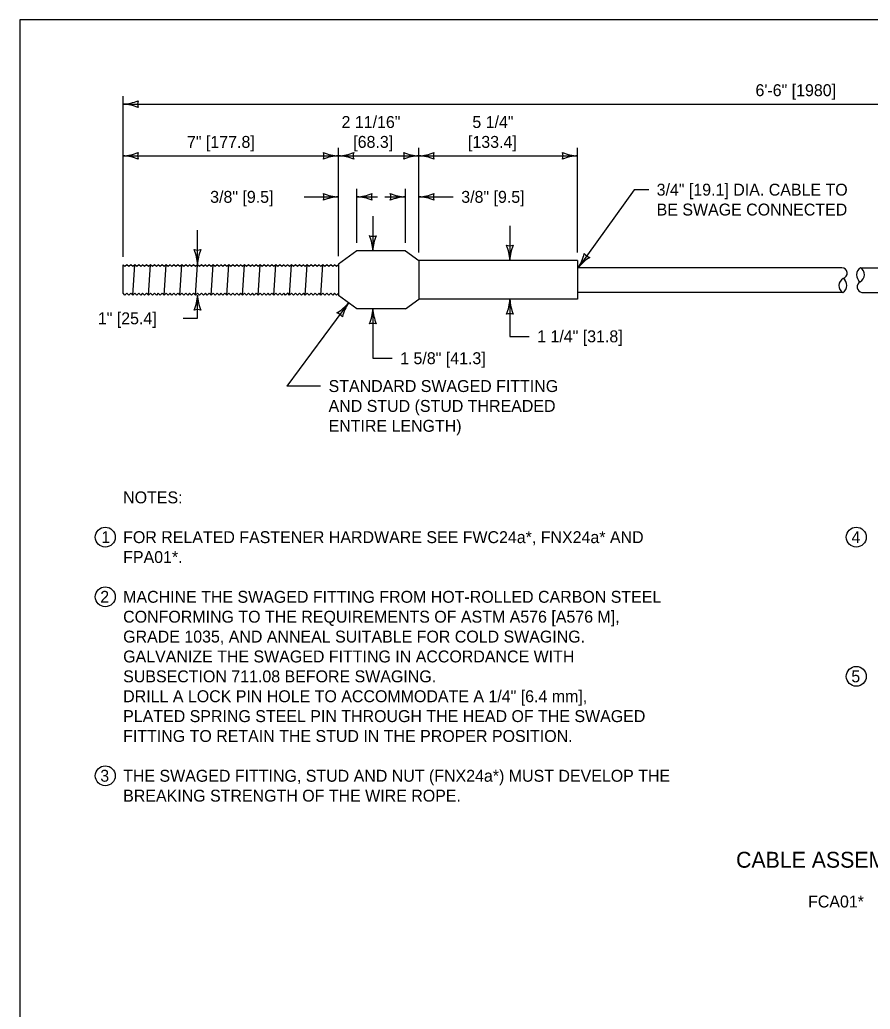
# Model space of a CAD drawing. Extents: x 49991.4 to 50021, y 49987.6 to 50011.4.
# Drawn here: x 50000.336 to 50004.612, y 50006.287 to 50011.263 of the extents above; entities that cross this region are included whole.
import ezdxf

# ---------------------------------------------------------------- set-up
doc = ezdxf.new("R2010")
doc.units = 0
for name, color, linetype in [('Level 1', 7, 'Continuous'), ('Level 2', 7, 'Continuous'), ('Level 3', 7, 'Continuous')]:
    doc.layers.add(name, color=color, linetype=linetype)

msp = doc.modelspace()

# ---------------------------------------------------------------- linework, layer by layer
at = {"layer": 'Level 1'}
for p, q in [((50002.0304, 50010.1011), (50001.9386, 50010.0335)), ((50002.2748, 50010.1011), (50002.0304, 50010.1011)), ((50002.2748, 50010.1011), (50002.3422, 50010.0531)), ((50002.3422, 50010.0531), (50002.3422, 50009.8577)), ((50003.1408, 50010.0531), (50002.3422, 50010.0531)), ((50003.1408, 50010.0531), (50003.1408, 50009.8577)), ((50000.8542, 50010.0181), (50000.8542, 50009.8915)), ((50000.8542, 50010.0181), (50000.8546, 50010.0181)), ((50000.8642, 50010.0213), (50000.8546, 50010.0311)), ((50000.8546, 50009.8883), (50000.8546, 50010.0311)), ((50000.8742, 50010.0311), (50000.8642, 50010.0213)), ((50000.8842, 50010.0213), (50000.8742, 50010.0311)), ((50000.8938, 50010.0311), (50000.8842, 50010.0213)), ((50000.9036, 50010.0213), (50000.8938, 50010.0311)), ((50000.9138, 50010.0311), (50000.9036, 50010.0213)), ((50000.9036, 50009.8785), (50000.9138, 50010.0311)), ((50000.9238, 50010.0213), (50000.9138, 50010.0311)), ((50000.9336, 50010.0311), (50000.9238, 50010.0213)), ((50000.9436, 50010.0213), (50000.9336, 50010.0311)), ((50000.9532, 50010.0311), (50000.9436, 50010.0213)), ((50000.963, 50010.0213), (50000.9532, 50010.0311)), ((50000.973, 50010.0311), (50000.963, 50010.0213)), ((50000.9828, 50010.0213), (50000.973, 50010.0311)), ((50000.9926, 50010.0311), (50000.9828, 50010.0213)), ((50000.9828, 50009.8785), (50000.9926, 50010.0311)), ((50001.0024, 50010.0213), (50000.9926, 50010.0311)), ((50001.0122, 50010.0311), (50001.0024, 50010.0213)), ((50001.0222, 50010.0213), (50001.0122, 50010.0311)), ((50001.032, 50010.0311), (50001.0222, 50010.0213)), ((50001.0418, 50010.0213), (50001.032, 50010.0311)), ((50001.0516, 50010.0311), (50001.0418, 50010.0213)), ((50001.0616, 50010.0213), (50001.0516, 50010.0311)), ((50001.0714, 50010.0311), (50001.0616, 50010.0213)), ((50001.0616, 50009.8785), (50001.0714, 50010.0311)), ((50001.0812, 50010.0213), (50001.0714, 50010.0311)), ((50001.091, 50010.0311), (50001.0812, 50010.0213)), ((50001.1008, 50010.0213), (50001.091, 50010.0311)), ((50001.1108, 50010.0311), (50001.1008, 50010.0213)), ((50001.1206, 50010.0213), (50001.1108, 50010.0311)), ((50001.1304, 50010.0311), (50001.1206, 50010.0213)), ((50001.1404, 50010.0213), (50001.1304, 50010.0311)), ((50001.1502, 50010.0311), (50001.1404, 50010.0213)), ((50001.1404, 50009.8785), (50001.1502, 50010.0311)), ((50001.1598, 50010.0213), (50001.1502, 50010.0311)), ((50001.1702, 50010.0311), (50001.1598, 50010.0213)), ((50001.1802, 50010.0213), (50001.1702, 50010.0311)), ((50001.1898, 50010.0311), (50001.1802, 50010.0213)), ((50001.1998, 50010.0213), (50001.1898, 50010.0311)), ((50001.2096, 50010.0311), (50001.1998, 50010.0213)), ((50001.2192, 50010.0213), (50001.2096, 50010.0311)), ((50001.2292, 50010.0311), (50001.2192, 50010.0213)), ((50001.2192, 50009.8785), (50001.2292, 50010.0311)), ((50001.239, 50010.0213), (50001.2292, 50010.0311)), ((50001.2488, 50010.0311), (50001.239, 50010.0213)), ((50001.2586, 50010.0213), (50001.2488, 50010.0311)), ((50001.2686, 50010.0311), (50001.2586, 50010.0213)), ((50001.2786, 50010.0213), (50001.2686, 50010.0311)), ((50001.2882, 50010.0311), (50001.2786, 50010.0213)), ((50001.298, 50010.0213), (50001.2882, 50010.0311)), ((50001.3078, 50010.0311), (50001.298, 50010.0213)), ((50001.298, 50009.8785), (50001.3078, 50010.0311)), ((50001.3178, 50010.0213), (50001.3078, 50010.0311)), ((50001.3276, 50010.0311), (50001.3178, 50010.0213)), ((50001.3374, 50010.0213), (50001.3276, 50010.0311)), ((50001.3472, 50010.0311), (50001.3374, 50010.0213)), ((50001.3572, 50010.0213), (50001.3472, 50010.0311)), ((50001.367, 50010.0311), (50001.3572, 50010.0213)), ((50001.3768, 50010.0213), (50001.367, 50010.0311)), ((50001.3866, 50010.0311), (50001.3768, 50010.0213)), ((50001.3768, 50009.8785), (50001.3866, 50010.0311)), ((50001.3966, 50010.0213), (50001.3866, 50010.0311)), ((50001.4064, 50010.0311), (50001.3966, 50010.0213)), ((50001.4162, 50010.0213), (50001.4064, 50010.0311)), ((50001.4264, 50010.0311), (50001.4162, 50010.0213)), ((50001.4364, 50010.0213), (50001.4264, 50010.0311)), ((50001.446, 50010.0311), (50001.4364, 50010.0213)), ((50001.456, 50010.0213), (50001.446, 50010.0311)), ((50001.4658, 50010.0311), (50001.456, 50010.0213)), ((50001.456, 50009.8785), (50001.4658, 50010.0311)), ((50001.4756, 50010.0213), (50001.4658, 50010.0311)), ((50001.4856, 50010.0311), (50001.4756, 50010.0213)), ((50001.4952, 50010.0213), (50001.4856, 50010.0311)), ((50001.5052, 50010.0311), (50001.4952, 50010.0213)), ((50001.5148, 50010.0213), (50001.5052, 50010.0311)), ((50001.5248, 50010.0311), (50001.5148, 50010.0213)), ((50001.5348, 50010.0213), (50001.5248, 50010.0311)), ((50001.5446, 50010.0311), (50001.5348, 50010.0213)), ((50001.5348, 50009.8785), (50001.5446, 50010.0311)), ((50001.5542, 50010.0213), (50001.5446, 50010.0311)), ((50001.5642, 50010.0311), (50001.5542, 50010.0213)), ((50001.574, 50010.0213), (50001.5642, 50010.0311)), ((50001.5838, 50010.0311), (50001.574, 50010.0213)), ((50001.5936, 50010.0213), (50001.5838, 50010.0311)), ((50001.6036, 50010.0311), (50001.5936, 50010.0213)), ((50001.6134, 50010.0213), (50001.6036, 50010.0311)), ((50001.6232, 50010.0311), (50001.6134, 50010.0213)), ((50001.6134, 50009.8785), (50001.6232, 50010.0311)), ((50001.633, 50010.0213), (50001.6232, 50010.0311)), ((50001.6428, 50010.0311), (50001.633, 50010.0213)), ((50001.6528, 50010.0213), (50001.6428, 50010.0311)), ((50001.6626, 50010.0311), (50001.6528, 50010.0213)), ((50001.6724, 50010.0213), (50001.6626, 50010.0311)), ((50001.6826, 50010.0311), (50001.6724, 50010.0213)), ((50001.6926, 50010.0213), (50001.6826, 50010.0311)), ((50001.7022, 50010.0311), (50001.6926, 50010.0213)), ((50001.6926, 50009.8785), (50001.7022, 50010.0311)), ((50001.7122, 50010.0213), (50001.7022, 50010.0311)), ((50001.722, 50010.0311), (50001.7122, 50010.0213)), ((50001.7318, 50010.0213), (50001.722, 50010.0311)), ((50001.7418, 50010.0311), (50001.7318, 50010.0213)), ((50001.7516, 50010.0213), (50001.7418, 50010.0311)), ((50001.7614, 50010.0311), (50001.7516, 50010.0213)), ((50001.7712, 50010.0213), (50001.7614, 50010.0311)), ((50001.781, 50010.0311), (50001.7712, 50010.0213)), ((50001.7712, 50009.8785), (50001.781, 50010.0311)), ((50001.791, 50010.0213), (50001.781, 50010.0311)), ((50001.8008, 50010.0311), (50001.791, 50010.0213)), ((50001.8106, 50010.0213), (50001.8008, 50010.0311)), ((50001.8204, 50010.0311), (50001.8106, 50010.0213)), ((50001.8302, 50010.0213), (50001.8204, 50010.0311)), ((50001.8402, 50010.0311), (50001.8302, 50010.0213)), ((50001.8498, 50010.0213), (50001.8402, 50010.0311)), ((50001.8598, 50010.0311), (50001.8498, 50010.0213)), ((50001.8498, 50009.8785), (50001.8598, 50010.0311)), ((50001.8696, 50010.0213), (50001.8598, 50010.0311)), ((50001.8796, 50010.0311), (50001.8696, 50010.0213)), ((50001.8892, 50010.0213), (50001.8796, 50010.0311)), ((50001.8992, 50010.0311), (50001.8892, 50010.0213)), ((50001.909, 50010.0213), (50001.8992, 50010.0311)), ((50001.9188, 50010.0311), (50001.909, 50010.0213)), ((50001.9286, 50010.0213), (50001.9188, 50010.0311)), ((50001.9386, 50010.0311), (50001.9286, 50010.0213)), ((50001.9386, 50010.0335), (50001.9386, 50009.8771)), ((50004.4692, 50010.0157), (50003.1408, 50010.0157)), ((50004.5624, 50010.0157), (50005.8048, 50010.0157)), ((50000.8542, 50009.8915), (50000.8546, 50009.8915)), ((50000.8642, 50009.8785), (50000.8546, 50009.8883)), ((50000.8742, 50009.8883), (50000.8642, 50009.8785)), ((50000.8842, 50009.8785), (50000.8742, 50009.8883)), ((50000.8938, 50009.8883), (50000.8842, 50009.8785)), ((50000.9036, 50009.8785), (50000.8938, 50009.8883)), ((50000.9138, 50009.8883), (50000.9036, 50009.8785)), ((50000.9238, 50009.8785), (50000.9138, 50009.8883)), ((50000.9336, 50009.8883), (50000.9238, 50009.8785)), ((50000.9436, 50009.8785), (50000.9336, 50009.8883)), ((50000.9532, 50009.8883), (50000.9436, 50009.8785)), ((50000.963, 50009.8785), (50000.9532, 50009.8883)), ((50000.973, 50009.8883), (50000.963, 50009.8785)), ((50000.9828, 50009.8785), (50000.973, 50009.8883)), ((50000.9926, 50009.8883), (50000.9828, 50009.8785)), ((50001.0024, 50009.8785), (50000.9926, 50009.8883)), ((50001.0122, 50009.8883), (50001.0024, 50009.8785)), ((50001.0222, 50009.8785), (50001.0122, 50009.8883)), ((50001.032, 50009.8883), (50001.0222, 50009.8785)), ((50001.0418, 50009.8785), (50001.032, 50009.8883)), ((50001.0516, 50009.8883), (50001.0418, 50009.8785)), ((50001.0616, 50009.8785), (50001.0516, 50009.8883)), ((50001.0714, 50009.8883), (50001.0616, 50009.8785)), ((50001.0812, 50009.8785), (50001.0714, 50009.8883)), ((50001.091, 50009.8883), (50001.0812, 50009.8785)), ((50001.1008, 50009.8785), (50001.091, 50009.8883)), ((50001.1108, 50009.8883), (50001.1008, 50009.8785)), ((50001.1206, 50009.8785), (50001.1108, 50009.8883)), ((50001.1304, 50009.8883), (50001.1206, 50009.8785)), ((50001.1404, 50009.8785), (50001.1304, 50009.8883)), ((50001.1502, 50009.8883), (50001.1404, 50009.8785)), ((50001.1598, 50009.8785), (50001.1502, 50009.8883)), ((50001.1702, 50009.8883), (50001.1598, 50009.8785)), ((50001.1802, 50009.8785), (50001.1702, 50009.8883)), ((50001.1898, 50009.8883), (50001.1802, 50009.8785)), ((50001.1998, 50009.8785), (50001.1898, 50009.8883)), ((50001.2096, 50009.8883), (50001.1998, 50009.8785)), ((50001.2192, 50009.8785), (50001.2096, 50009.8883)), ((50001.2292, 50009.8883), (50001.2192, 50009.8785)), ((50001.239, 50009.8785), (50001.2292, 50009.8883)), ((50001.2488, 50009.8883), (50001.239, 50009.8785)), ((50001.2586, 50009.8785), (50001.2488, 50009.8883)), ((50001.2686, 50009.8883), (50001.2586, 50009.8785)), ((50001.2786, 50009.8785), (50001.2686, 50009.8883)), ((50001.2882, 50009.8883), (50001.2786, 50009.8785)), ((50001.298, 50009.8785), (50001.2882, 50009.8883)), ((50001.3078, 50009.8883), (50001.298, 50009.8785)), ((50001.3178, 50009.8785), (50001.3078, 50009.8883)), ((50001.3276, 50009.8883), (50001.3178, 50009.8785)), ((50001.3374, 50009.8785), (50001.3276, 50009.8883)), ((50001.3472, 50009.8883), (50001.3374, 50009.8785)), ((50001.3572, 50009.8785), (50001.3472, 50009.8883)), ((50001.367, 50009.8883), (50001.3572, 50009.8785)), ((50001.3768, 50009.8785), (50001.367, 50009.8883)), ((50001.3866, 50009.8883), (50001.3768, 50009.8785)), ((50001.3966, 50009.8785), (50001.3866, 50009.8883)), ((50001.4064, 50009.8883), (50001.3966, 50009.8785)), ((50001.4162, 50009.8785), (50001.4064, 50009.8883)), ((50001.4264, 50009.8883), (50001.4162, 50009.8785)), ((50001.4364, 50009.8785), (50001.4264, 50009.8883)), ((50001.446, 50009.8883), (50001.4364, 50009.8785)), ((50001.456, 50009.8785), (50001.446, 50009.8883)), ((50001.4658, 50009.8883), (50001.456, 50009.8785)), ((50001.4756, 50009.8785), (50001.4658, 50009.8883)), ((50001.4856, 50009.8883), (50001.4756, 50009.8785)), ((50001.4952, 50009.8785), (50001.4856, 50009.8883)), ((50001.5052, 50009.8883), (50001.4952, 50009.8785)), ((50001.5148, 50009.8785), (50001.5052, 50009.8883)), ((50001.5248, 50009.8883), (50001.5148, 50009.8785)), ((50001.5348, 50009.8785), (50001.5248, 50009.8883)), ((50001.5446, 50009.8883), (50001.5348, 50009.8785)), ((50001.5542, 50009.8785), (50001.5446, 50009.8883)), ((50001.5642, 50009.8883), (50001.5542, 50009.8785)), ((50001.574, 50009.8785), (50001.5642, 50009.8883)), ((50001.5838, 50009.8883), (50001.574, 50009.8785)), ((50001.5936, 50009.8785), (50001.5838, 50009.8883)), ((50001.6036, 50009.8883), (50001.5936, 50009.8785)), ((50001.6134, 50009.8785), (50001.6036, 50009.8883)), ((50001.6232, 50009.8883), (50001.6134, 50009.8785)), ((50001.633, 50009.8785), (50001.6232, 50009.8883)), ((50001.6428, 50009.8883), (50001.633, 50009.8785)), ((50001.6528, 50009.8785), (50001.6428, 50009.8883)), ((50001.6626, 50009.8883), (50001.6528, 50009.8785)), ((50001.6724, 50009.8785), (50001.6626, 50009.8883)), ((50001.6826, 50009.8883), (50001.6724, 50009.8785)), ((50001.6926, 50009.8785), (50001.6826, 50009.8883)), ((50001.7022, 50009.8883), (50001.6926, 50009.8785)), ((50001.7122, 50009.8785), (50001.7022, 50009.8883)), ((50001.722, 50009.8883), (50001.7122, 50009.8785)), ((50001.7318, 50009.8785), (50001.722, 50009.8883)), ((50001.7418, 50009.8883), (50001.7318, 50009.8785)), ((50001.7516, 50009.8785), (50001.7418, 50009.8883)), ((50001.7614, 50009.8883), (50001.7516, 50009.8785)), ((50001.7712, 50009.8785), (50001.7614, 50009.8883)), ((50001.781, 50009.8883), (50001.7712, 50009.8785)), ((50001.791, 50009.8785), (50001.781, 50009.8883)), ((50001.8008, 50009.8883), (50001.791, 50009.8785)), ((50001.8106, 50009.8785), (50001.8008, 50009.8883)), ((50001.8204, 50009.8883), (50001.8106, 50009.8785)), ((50001.8302, 50009.8785), (50001.8204, 50009.8883)), ((50001.8402, 50009.8883), (50001.8302, 50009.8785)), ((50001.8498, 50009.8785), (50001.8402, 50009.8883)), ((50001.8598, 50009.8883), (50001.8498, 50009.8785)), ((50001.8696, 50009.8785), (50001.8598, 50009.8883)), ((50001.8796, 50009.8883), (50001.8696, 50009.8785)), ((50001.8892, 50009.8785), (50001.8796, 50009.8883)), ((50001.8992, 50009.8883), (50001.8892, 50009.8785)), ((50001.909, 50009.8785), (50001.8992, 50009.8883)), ((50001.9188, 50009.8883), (50001.909, 50009.8785)), ((50001.9286, 50009.8785), (50001.9188, 50009.8883)), ((50001.9386, 50009.8883), (50001.9286, 50009.8785)), ((50004.4746, 50009.8915), (50003.1408, 50009.8915)), ((50004.5692, 50009.8915), (50005.8048, 50009.8915)), ((50002.0304, 50009.8097), (50001.9386, 50009.8771)), ((50002.2748, 50009.8097), (50002.3422, 50009.8577)), ((50003.1408, 50009.8577), (50002.3422, 50009.8577)), ((50002.2748, 50009.8097), (50002.0304, 50009.8097))]:
    msp.add_line(p, q, dxfattribs=at)
msp.add_lwpolyline([(50008.6146, 50011.2628), (50000.3356, 50011.2628), (50000.3356, 50000.0624), (50008.6146, 50000.0624)], close=True, dxfattribs=at)
for centre, radius, start, end in [((50004.4687, 50009.9882), 0.0275, 285.9076, 88.9919), ((50004.5857, 50009.98), 0.0426, 123.141, 234.1603), ((50004.5431, 50009.981), 0.0397, 296.4514, 60.8498), ((50004.4939, 50009.9262), 0.0397, 116.4514, 240.8498), ((50004.4513, 50009.9272), 0.0426, 303.141, 54.1603), ((50004.5756, 50009.9201), 0.0293, 120.3565, 257.4562)]:
    msp.add_arc(centre, radius, start, end, dxfattribs=at)
at = {"layer": 'Level 2'}
for centre in [(50000.7654, 50008.661), (50004.5418, 50008.661), (50000.7654, 50008.361), (50004.5418, 50007.961), (50000.7654, 50007.461)]:
    msp.add_circle(centre, 0.05, dxfattribs=at)
at = {"layer": 'Level 3'}
for p, q in [((50000.8546, 50010.0711), (50000.8546, 50010.8787)), ((50000.8546, 50010.8387), (50004.735, 50010.8387)), ((50001.9386, 50010.0735), (50001.9386, 50010.6187)), ((50002.3422, 50010.0931), (50002.3422, 50010.6187)), ((50003.1408, 50010.0931), (50003.1408, 50010.6187)), ((50000.8546, 50010.5787), (50001.9386, 50010.5787)), ((50001.9386, 50010.5787), (50002.3498, 50010.5787)), ((50002.3498, 50010.5787), (50003.1408, 50010.5787)), ((50002.0304, 50010.1411), (50002.0304, 50010.4123)), ((50002.2748, 50010.1411), (50002.2748, 50010.4123)), ((50003.4248, 50010.4085), (50003.1435, 50010.0157)), ((50003.498, 50010.4085), (50003.4248, 50010.4085)), ((50001.7652, 50010.3723), (50001.9386, 50010.3723)), ((50002.0304, 50010.3723), (50002.1338, 50010.3723)), ((50002.1714, 50010.3723), (50002.2748, 50010.3723)), ((50002.3422, 50010.3723), (50002.5156, 50010.3723)), ((50002.111, 50010.2745), (50002.111, 50010.1011)), ((50001.2292, 50010.0311), (50001.2292, 50010.2045)), ((50002.7998, 50010.2265), (50002.7998, 50010.0531)), ((50001.2292, 50009.7615), (50001.2292, 50009.8785)), ((50001.9889, 50009.8402), (50001.6788, 50009.4209)), ((50002.8, 50009.8577), (50002.8, 50009.6709)), ((50002.111, 50009.8097), (50002.111, 50009.5609)), ((50001.1566, 50009.7615), (50001.2292, 50009.7615)), ((50002.8, 50009.6709), (50002.8972, 50009.6709)), ((50002.111, 50009.5609), (50002.2084, 50009.5609)), ((50001.8484, 50009.4209), (50001.6788, 50009.4209))]:
    msp.add_line(p, q, dxfattribs=at)
for centre, radius, start, end in [((50000.8431, 50011.0714), 0.233, 272.8273, 292.0772), ((50000.8454, 50010.6166), 0.2223, 67.456, 87.6395), ((50000.9828, 50010.8387), 0.0548, 162.1388, 197.8612), ((50000.8431, 50010.8114), 0.233, 272.8273, 292.0772), ((50000.9828, 50010.5787), 0.0548, 162.1388, 197.8612), ((50001.9478, 50010.8008), 0.2223, 247.456, 267.6395), ((50001.8104, 50010.5787), 0.0548, 342.1388, 17.8612), ((50001.9271, 50010.8114), 0.233, 272.8273, 292.0772), ((50002.0668, 50010.5787), 0.0548, 162.1388, 197.8612), ((50002.3514, 50010.8008), 0.2223, 247.456, 267.6395), ((50002.214, 50010.5787), 0.0548, 342.1388, 17.8612), ((50002.3307, 50010.8114), 0.233, 272.8273, 292.0772), ((50002.4704, 50010.5787), 0.0548, 162.1388, 197.8612), ((50003.15, 50010.8008), 0.2223, 247.456, 267.6395), ((50003.0126, 50010.5787), 0.0548, 342.1388, 17.8612), ((50000.8454, 50010.3566), 0.2223, 67.456, 87.6395), ((50001.9501, 50010.346), 0.233, 92.8273, 112.0772), ((50001.9294, 50010.3566), 0.2223, 67.456, 87.6395), ((50002.3537, 50010.346), 0.233, 92.8273, 112.0772), ((50002.333, 50010.3566), 0.2223, 67.456, 87.6395), ((50003.1523, 50010.346), 0.233, 92.8273, 112.0772), ((50001.9478, 50010.5944), 0.2223, 247.456, 267.6395), ((50001.8104, 50010.3723), 0.0548, 342.1388, 17.8612), ((50002.0189, 50010.605), 0.233, 272.8273, 292.0772), ((50002.1586, 50010.3723), 0.0548, 162.1388, 197.8612), ((50002.284, 50010.5944), 0.2223, 247.456, 267.6395), ((50002.1466, 50010.3723), 0.0548, 342.1388, 17.8612), ((50002.3307, 50010.605), 0.233, 272.8273, 292.0772), ((50002.4704, 50010.3723), 0.0548, 162.1388, 197.8612), ((50001.9501, 50010.1396), 0.233, 92.8273, 112.0772), ((50002.0212, 50010.1502), 0.2223, 67.456, 87.6395), ((50002.2863, 50010.1396), 0.233, 92.8273, 112.0772), ((50002.333, 50010.1502), 0.2223, 67.456, 87.6395), ((50002.111, 50010.2293), 0.0548, 252.1388, 287.8612), ((50001.8783, 50010.0896), 0.233, 2.8273, 22.0772), ((50002.3331, 50010.0919), 0.2223, 157.456, 177.6395), ((50001.2292, 50010.1593), 0.0548, 252.1388, 287.8612), ((50000.9965, 50010.0196), 0.233, 2.8273, 22.0772), ((50001.4513, 50010.0219), 0.2223, 157.456, 177.6395), ((50002.7998, 50010.1813), 0.0548, 252.1388, 287.8612), ((50002.5671, 50010.0416), 0.233, 2.8273, 22.0772), ((50003.0219, 50010.0439), 0.2223, 157.456, 177.6395), ((50002.9476, 50010.1418), 0.233, 327.2304, 346.4802), ((50003.2182, 50010.12), 0.0548, 216.5419, 252.2643), ((50003.3188, 50009.879), 0.2223, 121.8591, 142.0426), ((50001.0071, 50009.8877), 0.2223, 337.456, 357.6395), ((50001.4619, 50009.89), 0.233, 182.8273, 202.0772), ((50001.8147, 50009.9783), 0.2223, 301.4073, 321.5908), ((50002.1838, 50009.7125), 0.233, 146.7786, 166.0285), ((50002.5779, 50009.8669), 0.2223, 337.456, 357.6395), ((50003.0327, 50009.8692), 0.233, 182.8273, 202.0772), ((50001.2292, 50009.7503), 0.0548, 72.1388, 107.8612), ((50001.9135, 50009.7365), 0.0548, 36.0901, 71.8125), ((50001.8889, 50009.8189), 0.2223, 337.456, 357.6395), ((50002.3437, 50009.8212), 0.233, 182.8273, 202.0772), ((50002.111, 50009.6815), 0.0548, 72.1388, 107.8612), ((50002.8, 50009.7295), 0.0548, 72.1388, 107.8612)]:
    msp.add_arc(centre, radius, start, end, dxfattribs=at)

# ---------------------------------------------------------------- texts
at = {"layer": 'Level 2'}
for s, height, p in [('6\'-6" [1980]', 0.06, (50004.035, 50010.8787)), ('2 11/16"', 0.06, (50001.9535, 50010.7187)), ('5 1/4"', 0.06, (50002.6113, 50010.7187)), ('7" [177.8]', 0.06, (50001.1764, 50010.6187)), ('[68.3]', 0.06, (50002.0124, 50010.6187)), ('[133.4]', 0.06, (50002.5894, 50010.6187)), ('3/4" [19.1] DIA. CABLE TO ', 0.06, (50003.538, 50010.3785)), ('3/8" [9.5]', 0.06, (50001.2929, 50010.3423)), ('3/8" [9.5]', 0.06, (50002.5556, 50010.3423)), ('BE SWAGE CONNECTED', 0.06, (50003.538, 50010.2785)), ('1" [25.4]', 0.06, (50000.728, 50009.7315)), ('1 1/4" [31.8]', 0.06, (50002.9372, 50009.6409)), ('1 5/8" [41.3]', 0.06, (50002.2484, 50009.5309)), ('STANDARD SWAGED FITTING', 0.06, (50001.8884, 50009.3909)), ('AND STUD (STUD THREADED', 0.06, (50001.8884, 50009.2909)), ('ENTIRE LENGTH)', 0.06, (50001.8884, 50009.1909)), ('NOTES:', 0.06, (50000.8554, 50008.831)), ('1', 0.06, (50000.7456, 50008.631)), ('FOR RELATED FASTENER HARDWARE SEE FWC24a*, FNX24a* AND', 0.06, (50000.8554, 50008.631)), ('4', 0.06, (50004.5178, 50008.6311)), ('FPA01*.', 0.06, (50000.8554, 50008.531)), ('2', 0.06, (50000.7402, 50008.331)), ('MACHINE THE SWAGED FITTING FROM HOT-ROLLED CARBON STEEL', 0.06, (50000.8554, 50008.331)), ('CONFORMING TO THE REQUIREMENTS OF ASTM A576 [A576 M], ', 0.06, (50000.8554, 50008.231)), ('GRADE 1035, AND ANNEAL SUITABLE FOR COLD SWAGING. ', 0.06, (50000.8554, 50008.131)), ('GALVANIZE THE SWAGED FITTING IN ACCORDANCE WITH ', 0.06, (50000.8554, 50008.031)), ('SUBSECTION 711.08 BEFORE SWAGING. ', 0.06, (50000.8554, 50007.931)), ('5', 0.06, (50004.5169, 50007.931)), ('DRILL A LOCK PIN HOLE TO ACCOMMODATE A 1/4" [6.4 mm], ', 0.06, (50000.8554, 50007.831)), ('PLATED SPRING STEEL PIN THROUGH THE HEAD OF THE SWAGED', 0.06, (50000.8554, 50007.731)), ('FITTING TO RETAIN THE STUD IN THE PROPER POSITION.', 0.06, (50000.8554, 50007.631)), ('3', 0.06, (50000.7402, 50007.4311)), ('THE SWAGED FITTING, STUD AND NUT (FNX24a*) MUST DEVELOP THE', 0.06, (50000.8554, 50007.431)), ('BREAKING STRENGTH OF THE WIRE ROPE.', 0.06, (50000.8554, 50007.331)), ('CABLE ASSEMBLY', 0.08, (50003.9374, 50006.9986)), ('FCA01*', 0.06, (50004.2994, 50006.7986))]:
    msp.add_text(s, height=height, dxfattribs=at).set_placement(p)

doc.saveas('drawing.dxf')
